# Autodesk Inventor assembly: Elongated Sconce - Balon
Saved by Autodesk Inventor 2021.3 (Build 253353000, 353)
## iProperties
Created: 2022-08
Part Number: Elongated Sconce - Balon
Document SubType Name: Assembly
Designer: Administrator
Title: Elongated Sconce - Balon v6
Author: Administrator
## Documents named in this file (11)
- c:\worker\convert-fusion-r04\tmp\job-1\85\output\files\6d39c725-07d9-410a-aee3-1034c34b989b\5d74a80e-3826-44ac-8862-942dd6259861.iam
- c:\worker\convert-fusion-r04\tmp\job-1\85\output\files\6d39c725-07d9-410a-aee3-1034c34b989b\Back Plate.ipt
- c:\worker\convert-fusion-r04\tmp\job-1\85\output\files\6d39c725-07d9-410a-aee3-1034c34b989b\Knurled Shade Ring.ipt
- c:\worker\convert-fusion-r04\tmp\job-1\85\output\files\6d39c725-07d9-410a-aee3-1034c34b989b\Screw Top.ipt
- c:\worker\convert-fusion-r04\tmp\job-1\85\output\files\6d39c725-07d9-410a-aee3-1034c34b989b\Sconce.ipt
- c:\worker\convert-fusion-r04\tmp\job-1\85\output\files\6d39c725-07d9-410a-aee3-1034c34b989b\Socket Cover.ipt
- c:\worker\convert-fusion-r04\tmp\job-1\85\output\files\6d39c725-07d9-410a-aee3-1034c34b989b\Screw Bottom.ipt
- c:\worker\convert-fusion-r04\tmp\job-1\85\output\files\6d39c725-07d9-410a-aee3-1034c34b989b\Socket - E26.ipt
- c:\worker\convert-fusion-r04\tmp\job-1\85\output\files\6d39c725-07d9-410a-aee3-1034c34b989b\T9-Bulb.ipt
- c:\worker\convert-fusion-r04\tmp\job-1\85\output\files\6d39c725-07d9-410a-aee3-1034c34b989b\E26 Base.ipt
- c:\worker\convert-fusion-r04\tmp\job-1\85\output\files\6d39c725-07d9-410a-aee3-1034c34b989b\Part20.ipt
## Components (10 placed, 10 different names)
1. Back Plate:1
2. Knurled Shade Ring:1
3. Screw Top:1
4. Sconce:1
5. Socket Cover:1
6. Screw Bottom:1
7. Socket - E26:1
8. T9-Bulb:1
9. E26 Base:1
10. Part20
